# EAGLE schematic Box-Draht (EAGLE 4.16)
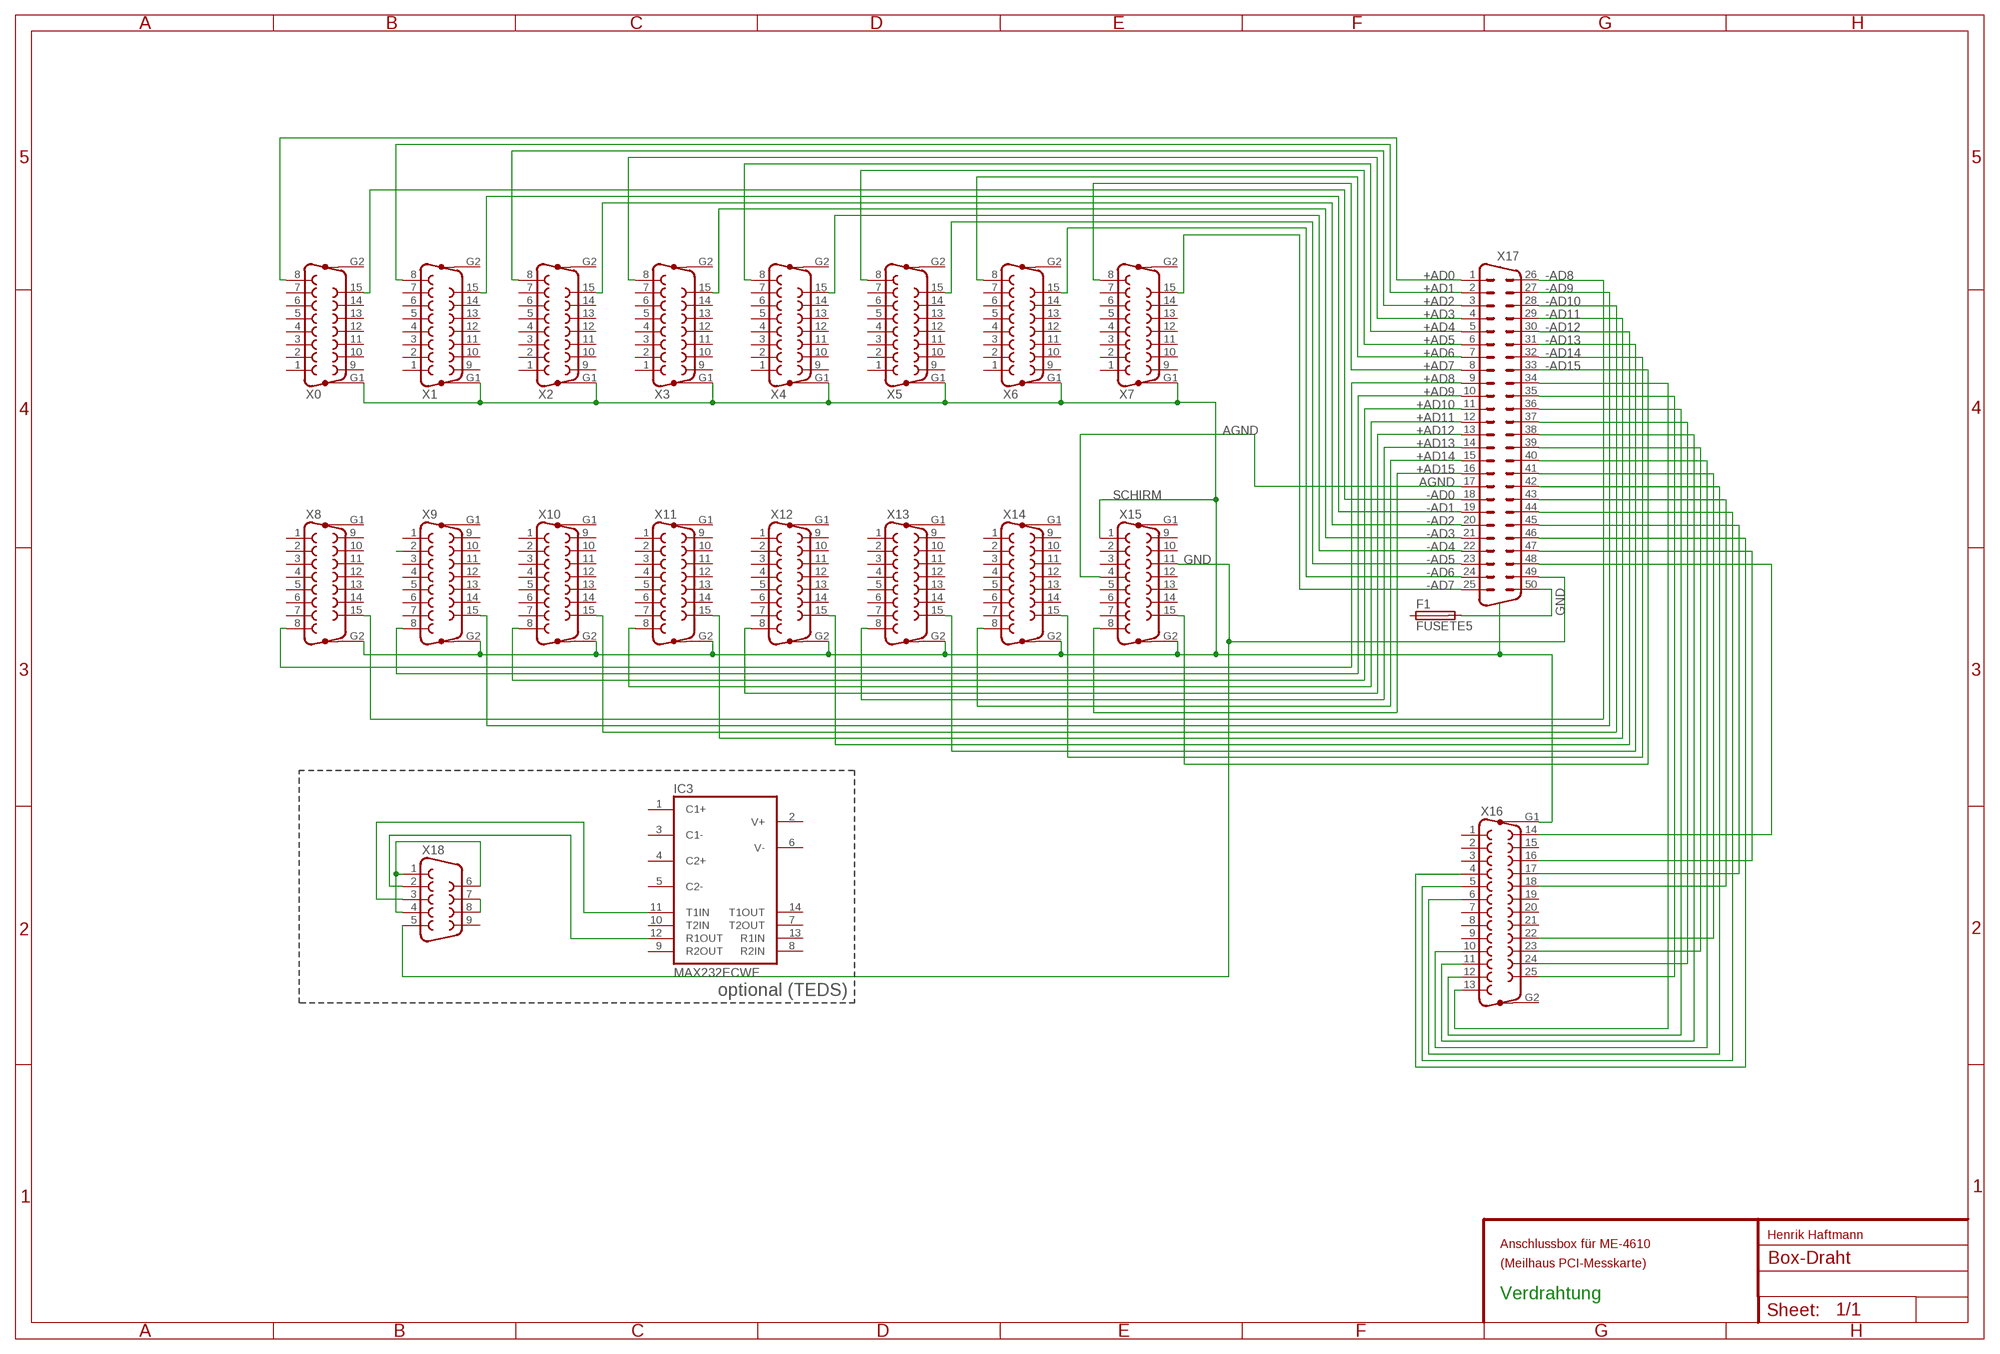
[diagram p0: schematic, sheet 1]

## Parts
F1  FUSETE5  [TE5]
IC3  MAX232ECWE  [SO16L]
X0  F15VP  [F15VP]
X1  F15VP  [F15VP]
X2  F15VP  [F15VP]
X3  F15VP  [F15VP]
X4  F15VP  [F15VP]
X5  F15VP  [F15VP]
X6  F15VP  [F15VP]
X7  F15VP  [F15VP]
X8  F15VP  [F15VP]
X9  F15VP  [F15VP]
X10  F15VP  [F15VP]
X11  F15VP  [F15VP]
X12  F15VP  [F15VP]
X13  F15VP  [F15VP]
X14  F15VP  [F15VP]
X15  F15VP  [F15VP]
X16  F25VP  [F25VP]
X17  M50V  [M50V]
X18  F09V  [F09V]

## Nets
+AD0: X0.8 X17.1
+AD1: X1.8 X17.2
+AD2: X2.8 X17.3
+AD3: X3.8 X17.4
+AD4: X4.8 X17.5
+AD5: X5.8 X17.6
+AD6: X6.8 X17.7
+AD7: X7.8 X17.8
+AD8: X8.8 X17.9
+AD9: X9.8 X17.10
+AD10: X10.8 X17.11
+AD11: X11.8 X17.12
+AD12: X12.8 X17.13
+AD13: X13.8 X17.14
+AD14: X14.8 X17.15
+AD15: X15.8 X17.16
-AD0: X0.15 X17.18
-AD1: X1.15 X17.19
-AD2: X2.15 X17.20
-AD3: X3.15 X17.21
-AD4: X4.15 X17.22
-AD5: X5.15 X17.23
-AD6: X6.15 X17.24
-AD7: X7.15 X17.25
-AD8: X8.15 X17.26
-AD9: X9.15 X17.27
-AD10: X10.15 X17.28
-AD11: X11.15 X17.29
-AD12: X12.15 X17.30
-AD13: X13.15 X17.31
-AD14: X14.15 X17.32
-AD15: X15.15 X17.33
AGND: X15.4 X17.17
GND: X15.11 X17.49 X18.5
N$2: F1.2 X17.50
N$3: X16.13 X17.34
N$4: X9.2
N$5: X16.25 X17.35
N$6: X16.12 X17.36
N$7: X16.24 X17.37
N$8: X16.11 X17.38
N$9: X16.23 X17.39
N$10: X16.10 X17.40
N$11: X16.22 X17.41
N$12: X16.6 X17.42
N$13: X16.18 X17.43
N$14: X16.5 X17.44
N$15: X16.17 X17.45
N$16: X16.4 X17.46
N$17: X16.16 X17.47
N$18: X16.14 X17.48
N$19: IC3.12(R1OUT) X18.2
N$20: IC3.11(T1IN) X18.3
N$21: X18.7 X18.8
N$22: X18.1 X18.4 X18.6
SCHIRM: X0.G1 X1.G1 X2.G1 X3.G1 X4.G1 X5.G1 X6.G1 X7.G1 X8.G2 X9.G2 X10.G2 X11.G2 X12.G2 X13.G2 X14.G2 X15.1 X15.G2 X16.G1
Unconnected: F1.1 IC3.1(C1+) IC3.2(V+) IC3.3(C1-) IC3.4(C2+) IC3.5(C2-) IC3.6(V-) IC3.7(T2OUT) IC3.8(R2IN) IC3.9(R2OUT) IC3.10(T2IN) IC3.13(R1IN) IC3.14(T1OUT) X0.1 X0.2 X0.3 X0.4 X0.5 X0.6 X0.7 X0.9 X0.10 X0.11 X0.12 X0.13 X0.14 X0.G2 X1.1 X1.2 X1.3 X1.4 X1.5 X1.6 X1.7 X1.9 X1.10 X1.11 X1.12 X1.13 X1.14 X1.G2 X2.1 X2.2 X2.3 X2.4 X2.5 X2.6 X2.7 X2.9 X2.10 X2.11 X2.12 X2.13 X2.14 X2.G2 X3.1 X3.2 X3.3 X3.4 X3.5 X3.6 X3.7 X3.9 X3.10 X3.11 X3.12 X3.13 X3.14 X3.G2 X4.1 X4.2 X4.3 X4.4 X4.5 X4.6 X4.7 X4.9 X4.10 X4.11 X4.12 X4.13 X4.14 X4.G2 X5.1 X5.2 X5.3 X5.4 X5.5 X5.6 X5.7 X5.9 X5.10 X5.11 X5.12 X5.13 X5.14 X5.G2 X6.1 X6.2 X6.3 X6.4 X6.5 X6.6 X6.7 X6.9 X6.10 X6.11 X6.12 X6.13 X6.14 X6.G2 X7.1 X7.2 X7.3 X7.4 X7.5 X7.6 X7.7 X7.9 X7.10 X7.11 X7.12 X7.13 X7.14 X7.G2 X8.1 X8.2 X8.3 X8.4 X8.5 X8.6 X8.7 X8.9 X8.10 X8.11 X8.12 X8.13 X8.14 X8.G1 X9.1 X9.3 X9.4 X9.5 X9.6 X9.7 X9.9 X9.10 X9.11 X9.12 X9.13 X9.14 X9.G1 X10.1 X10.2 X10.3 X10.4 X10.5 X10.6 X10.7 X10.9 X10.10 X10.11 X10.12 X10.13 X10.14 X10.G1 X11.1 X11.2 X11.3 X11.4 X11.5 X11.6 X11.7 X11.9 X11.10 X11.11 X11.12 X11.13 X11.14 X11.G1 X12.1 X12.2 X12.3 X12.4 X12.5 X12.6 X12.7 X12.9 X12.10 X12.11 X12.12 X12.13 X12.14 X12.G1 X13.1 X13.2 X13.3 X13.4 X13.5 X13.6 X13.7 X13.9 X13.10 X13.11 X13.12 X13.13 X13.14 X13.G1 X14.1 X14.2 X14.3 X14.4 X14.5 X14.6 X14.7 X14.9 X14.10 X14.11 X14.12 X14.13 X14.14 X14.G1 X15.2 X15.3 X15.5 X15.6 X15.7 X15.9 X15.10 X15.12 X15.13 X15.14 X15.G1 X16.1 X16.2 X16.3 X16.7 X16.8 X16.9 X16.15 X16.19 X16.20 X16.21 X16.G2 X18.9

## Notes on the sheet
- optional (TEDS)
- Henrik Haftmann
- Anschlussbox für ME-4610
- (Meilhaus PCI-Messkarte)
- Verdrahtung

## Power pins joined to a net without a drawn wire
GND: IC3.15(GND)
VCC: IC3.16(VCC)

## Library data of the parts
F1 = fuse:FUSE: Fuse
IC3 = maxim:MAX232ECWE: RS232 TRANSEIVER
X0 X1-X15 = con-subd:F15VP: SUB-D
X16 = con-subd:F25VP: SUB-D
X17 = con-subd:M50: SUB-D
X18 = con-subd:F09: SUB-D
